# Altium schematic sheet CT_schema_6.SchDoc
size 363 x 340 mm
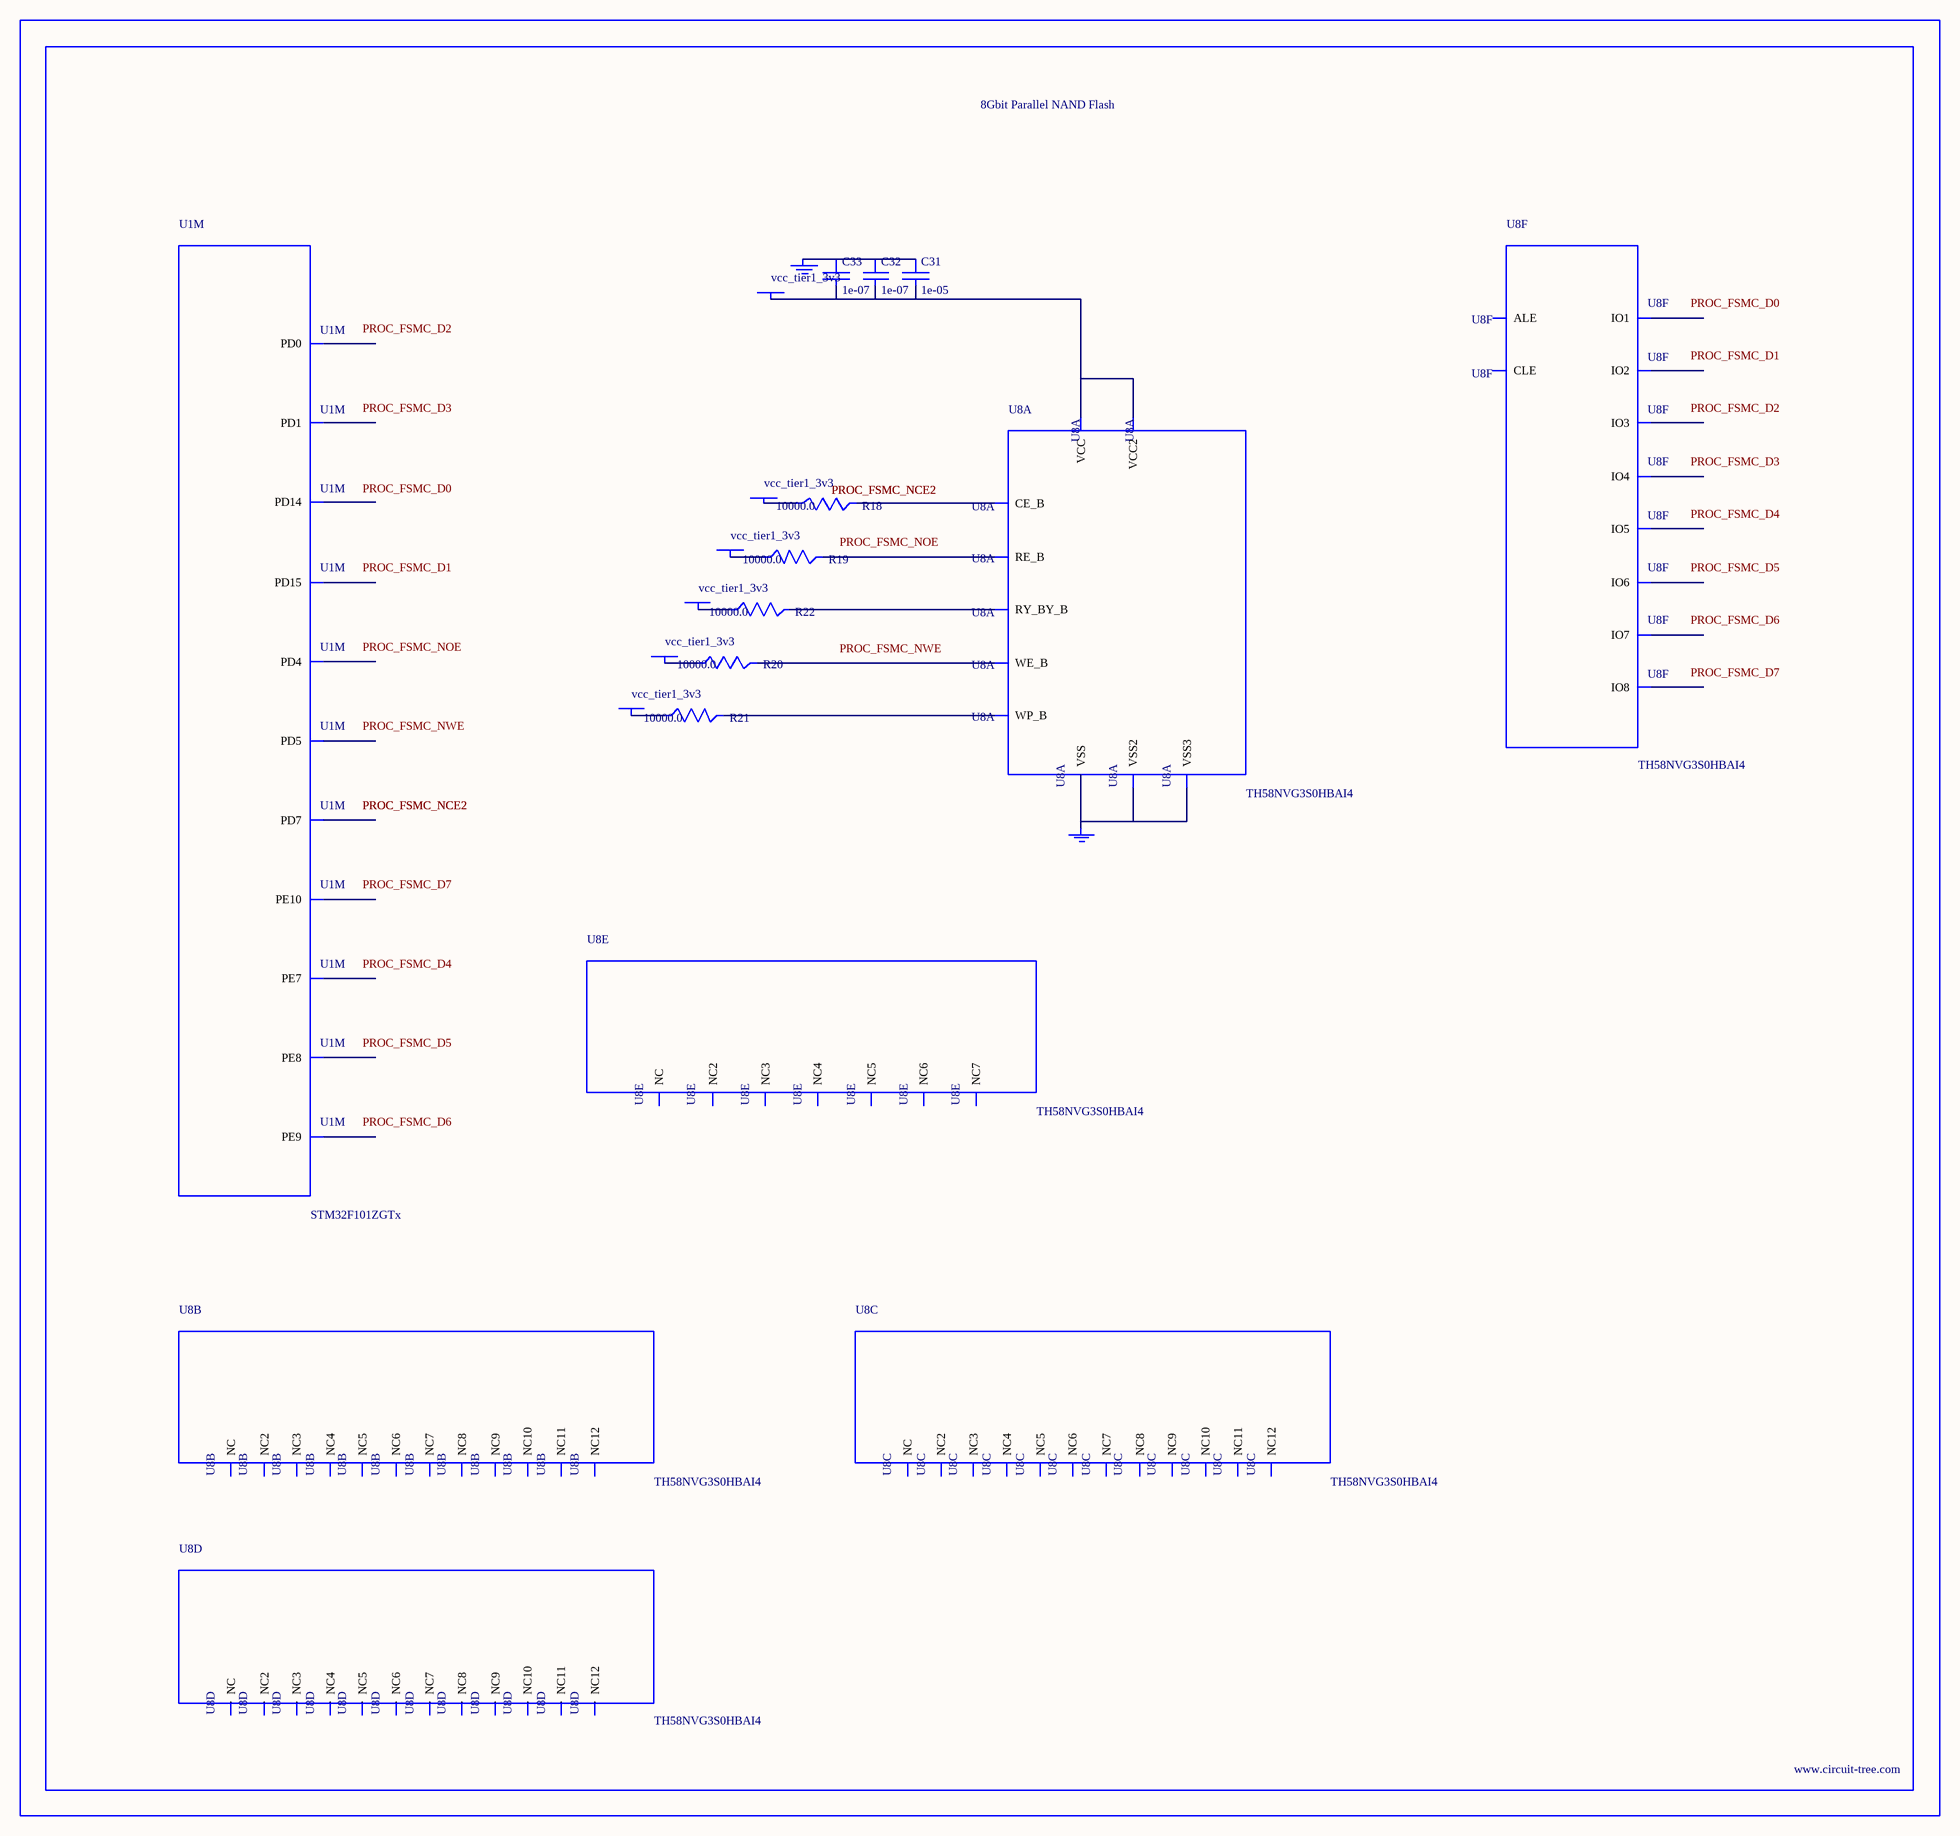
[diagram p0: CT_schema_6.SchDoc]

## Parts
BORDER5  (no value)
C31  1e-05  [C0805]
C32  1e-07  [C0402]
C33  1e-07  [C0402]
GND_INSTANCE_5_0  (no value)
GND_INSTANCE_5_1  (no value)
POWER_INSTANCE_5_0  vcc_tier1_3v3
POWER_INSTANCE_5_1  vcc_tier1_3v3
POWER_INSTANCE_5_2  vcc_tier1_3v3
POWER_INSTANCE_5_3  vcc_tier1_3v3
POWER_INSTANCE_5_4  vcc_tier1_3v3
POWER_INSTANCE_5_5  vcc_tier1_3v3
R18  10000.0  [R0603]
R19  10000.0  [R0603]
R20  10000.0  [R0603]
R21  10000.0  [R0603]
R22  10000.0  [R0603]
U1  STM32F101ZGTx  [LQFP144]  (part M of 13)
U8  TH58NVG3S0HBAI4  [TH58NVG3S0HBAI4]  (parts A,B,C,D,E,F of 6)

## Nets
NetC31_1: C31.1 C32.1 C33.1 GND_INSTANCE_5_0.0(GND)
NetC31_2: C31.2 C32.2 C33.2 POWER_INSTANCE_5_5.0(PWR) U8.H8(VCC) U8.J6(VCC2)
NetGND_INSTANCE_5_1_0: GND_INSTANCE_5_1.0(GND) U8.C5(VSS) U8.K3(VSS2) U8.K8(VSS3)
NetPOWER_INSTANCE_5_0_0: POWER_INSTANCE_5_0.0(PWR) R18.1
NetPOWER_INSTANCE_5_1_0: POWER_INSTANCE_5_1.0(PWR) R19.1
NetPOWER_INSTANCE_5_2_0: POWER_INSTANCE_5_2.0(PWR) R20.1
NetPOWER_INSTANCE_5_3_0: POWER_INSTANCE_5_3.0(PWR) R21.1
NetPOWER_INSTANCE_5_4_0: POWER_INSTANCE_5_4.0(PWR) R22.1
NetR18_2: R18.2 U8.C6(CE_B)
NetR19_2: R19.2 U8.D4(RE_B)
NetR20_2: R20.2 U8.C7(WE_B)
NetR21_2: R21.2 U8.C3(WP_B)
NetR22_2: R22.2 U8.C8(RY_BY_B)

Not connected (* = marked no-connect by the designer): U1 58(PE7) 59(PE8) 60(PE9) 63(PE10) 85(PD14) 86(PD15) 114(PD0) 115(PD1) 118(PD4) 119(PD5) 123(PD7); U8 A1(NC) A2(NC3) A9(NC4) A10(NC2) B1(NC5) B9(NC7) B10(NC6) C4(ALE) D3(NC8) D5(CLE) D6(NC9) D7(NC10) D8(NC11) E3(NC12) E4(NC) E5(NC2) E6(NC3) E7(NC4) E8(NC5) F3(NC6) F4(NC7) F5(NC8) F6(NC9) F7(NC10) F8(NC11) G3(NC12) G4(NC) G5(NC2) G6(NC3) G7(NC4) G8(NC5) H3(NC6) H4(IO1) H5(NC7) H6(NC8) H7(NC9) J3(NC10) J4(IO2) J5(NC11) J7(IO6) J8(IO8) K4(IO3) K5(IO4) K6(IO5) K7(IO7) L1(NC12) L2(NC2) L9(NC3) L10(NC) M1(NC4) M2(NC6) M9(NC7) M10(NC5)

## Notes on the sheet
- Labels drawn without touching a wire or pin: PROC_FSMC_D0, PROC_FSMC_D1, PROC_FSMC_D2, PROC_FSMC_D3, PROC_FSMC_D4, PROC_FSMC_D5, PROC_FSMC_D6, PROC_FSMC_D7, PROC_FSMC_NOE, PROC_FSMC_NWE

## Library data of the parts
BORDER5 = BORDER_PAGE5
C31 = C0805C106K8RACTU
C32 C33 = C0402C104K3RACTU
GND_INSTANCE_5_0 GND_INSTANCE_5_1 = GND
POWER_INSTANCE_5_0-POWER_INSTANCE_5_5 = PWR
R18-R22 = RC0603JR-0710KL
